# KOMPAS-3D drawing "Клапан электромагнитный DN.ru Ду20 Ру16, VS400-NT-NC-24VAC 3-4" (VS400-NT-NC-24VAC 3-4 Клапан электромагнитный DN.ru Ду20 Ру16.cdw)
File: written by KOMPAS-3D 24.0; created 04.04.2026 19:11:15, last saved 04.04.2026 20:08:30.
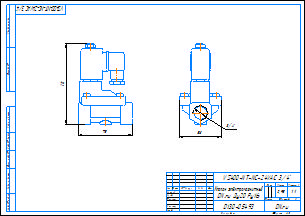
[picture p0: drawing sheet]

Document properties: c3d_UniqueCompID: ef56311e-7521-43dc-8291-0e6108b3d81d; Обозначение: VS400-ET-NC-220VAC 1-2; Наименование: Клапан электромагнитный DN.ru Ду15 Ру16; Автор: artio; Класс точности: c; Знак неуказанной шероховатости: Шероховатость не задана; Рассекать на разрезах: Да; c3d_UniqueCompID: ef56311e-7521-43dc-8291-0e6108b3d81d; Обозначение: VS400-ET-NC-220VAC 3-4; Наименование: Клапан электромагнитный DN.ru Ду20 Ру16; Автор: artio; Класс точности: c; Знак неуказанной шероховатости: Шероховатость не задана; Рассекать на разрезах: Да; c3d_UniqueCompID: ef56311e-7521-43dc-8291-0e6108b3d81d; Обозначение: VS400-ET-NC-220VAC 3-8; Наименование: Клапан электромагнитный DN.ru Ду10 Ру16; Автор: artio; Класс точности: c; Знак неуказанной шероховатости: Шероховатость не задана; Рассекать на разрезах: Да; Автор: artio; Форматы листов документа: A3; Полное имя файла: VS400-NT-NC-24VAC 3-4 Клапан электромагнитный DN.ru Ду20 Ру16.m3d; Масса: 0.954; Наименование: Клапан электромагнитный DN.ru Ду20 Ру16; Количество листов документа: 1; Примечание: D130-05493

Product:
- Body: Тело 1  | qty 1
    Масса: 1.210539
- Part/product: Клапан электромагнитный DN.ru Ду20 Ру16  | designation VS400-NT-NC-24VAC 3-4
    Масса: 0.954
    Раздел спецификации: Прочие изделия
    Примечание: D130-05493
    additional columns: ef56311e-7521-43dc-8291-0e6108b3d81d; VS400-ET-NC-220VAC 3-4; artio; c; Шероховатость не задана; Да

Views: Вид 1, Спереди, Проекционный вид 2
Referenced files in C:\Users\artio\OneDrive\Рабочий стол\Клапан электромагнитный DN.ru\VS400-ET-NC\VS400-ET-NC-24VDC\: VS400-ET-NC-24VDC 3-8 Клапан электромагнитный DN.ru Ду10 Ру16.m3d
Referenced files in C:\Users\artio\OneDrive\Рабочий стол\Клапан электромагнитный DN.ru\VS400-NT-NC\VS400-NT-NC-24VAC\: VS400-NT-NC-24VAC 3-4 Клапан электромагнитный DN.ru Ду20 Ру16.m3d
Referenced files in C:\Users\artio\OneDrive\Рабочий стол\Клапан электромагнитный DN.ru\VS400-ET-NC\: VS400-ET-NC-24VDC 3-8 Клапан электромагнитный DN.ru Ду10 Ру16.cdw
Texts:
  VS400-NT-NC-24VAC 3-4
  Клапан электромагнитный
  DN.ru Ду20 Ру16
  VS400-NT-NC-24VAC 3/4"
  VS400-NT-NC-24VAC 3/4"-
  Клапан электромагнитный DN.ru Ду20 Ру16
  VS400-NT-NC-24VAC 3-4 Клапан электромагнитный DN.ru Ду20 Ру16
Dimensions and other numbers on the sheet: 0; 3; 2; 4; 58; 3/4"; 75; 112; 1:1; 1; 0,95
